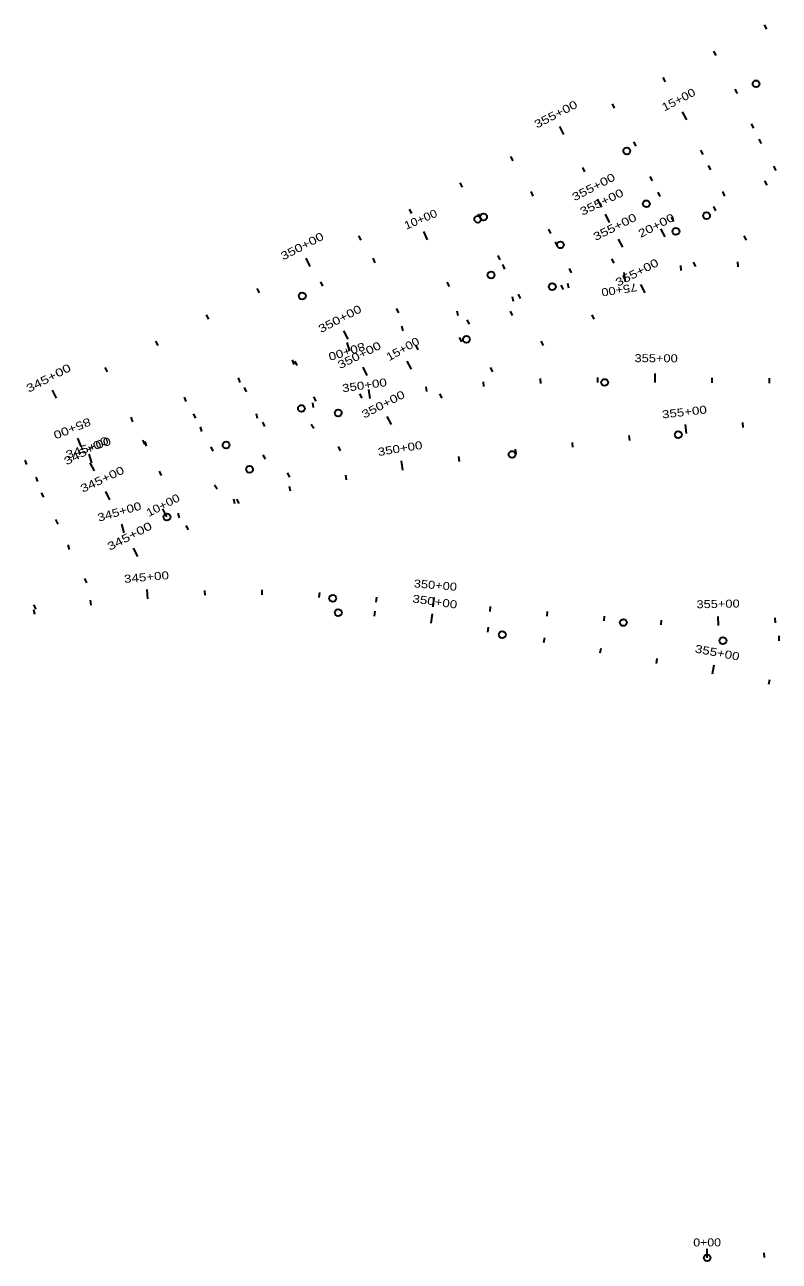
# Model space of a CAD drawing. Extents: x 2357892 to 2370172, y 6966790 to 6985499.
# Drawn here: x 2361944 to 2363264, y 6976486 to 6978648 of the extents above; entities that cross this region are included whole.
import ezdxf
from ezdxf.enums import TextEntityAlignment as Align

# ---------------------------------------------------------------- set-up
doc = ezdxf.new("R2010")
doc.units = 0
doc.header["$LTSCALE"] = 5.6
doc.layers.add('28', color=7, linetype='Continuous', lineweight=35)

msp = doc.modelspace()

# ---------------------------------------------------------------- linework, layer by layer
at = {"layer": '28'}
for p, q in [((2363242.374, 6978640.511), (2363238.454, 6978648.053)), ((2363153.644, 6978594.392), (2363149.724, 6978601.934)), ((2363064.914, 6978548.274), (2363060.994, 6978555.816)), ((2363190.97, 6978527.822), (2363187.05, 6978535.364)), ((2362976.183, 6978502.155), (2362972.263, 6978509.697)), ((2363102.237, 6978481.707), (2363094.859, 6978495.905)), ((2362887.453, 6978456.036), (2362880.074, 6978470.233)), ((2363219.718, 6978467.255), (2363215.798, 6978474.797)), ((2363233.133, 6978440.469), (2363229.189, 6978447.998)), ((2363013.505, 6978435.593), (2363009.585, 6978443.135)), ((2363130.985, 6978421.141), (2363127.065, 6978428.683)), ((2362798.723, 6978409.918), (2362794.803, 6978417.46)), ((2362924.238, 6978390.521), (2362920.535, 6978398.172)), ((2363042.252, 6978375.026), (2363038.333, 6978382.569)), ((2363144.553, 6978394.063), (2363140.608, 6978401.592)), ((2363258.451, 6978393.371), (2363254.64, 6978400.969)), ((2362709.992, 6978363.799), (2362706.072, 6978371.341)), ((2363242.718, 6978367.239), (2363238.902, 6978374.834)), ((2362833.477, 6978348.54), (2362830.043, 6978356.316)), ((2362953.52, 6978328.912), (2362946.142, 6978343.109)), ((2363055.972, 6978347.657), (2363052.028, 6978355.186)), ((2363169.063, 6978348.538), (2363165.253, 6978356.136)), ((2362621.262, 6978317.681), (2362617.342, 6978325.223)), ((2362741.308, 6978309.747), (2362738.132, 6978317.632)), ((2363153.362, 6978322.344), (2363149.546, 6978329.939)), ((2362966.869, 6978302.276), (2362959.897, 6978316.677)), ((2363079.676, 6978303.706), (2363075.865, 6978311.304)), ((2362532.532, 6978271.562), (2362528.611, 6978279.104)), ((2362648.849, 6978271.651), (2362642.625, 6978286.391)), ((2362864.787, 6978282.798), (2362860.868, 6978290.34)), ((2363064.251, 6978276.967), (2363056.918, 6978291.188)), ((2363206.786, 6978271.571), (2363202.867, 6978279.114)), ((2362875.943, 6978260.671), (2362872.556, 6978268.467)), ((2362990.289, 6978258.874), (2362983.116, 6978273.176)), ((2362443.801, 6978225.444), (2362436.422, 6978239.64)), ((2362557.068, 6978231.95), (2362553.625, 6978239.721)), ((2362776.055, 6978236.684), (2362772.135, 6978244.226)), ((2362975.372, 6978231.137), (2362971.476, 6978238.692)), ((2363118.045, 6978225.472), (2363114.127, 6978233.015)), ((2363191.153, 6978233.232), (2363191.43, 6978224.736)), ((2362784.224, 6978220.825), (2362780.838, 6978228.621)), ((2362900.902, 6978214.042), (2362897.091, 6978221.639)), ((2362992.154, 6978214.527), (2362994.621, 6978198.718)), ((2363091.368, 6978226.919), (2363092.163, 6978218.456)), ((2362465.994, 6978190.652), (2362462.416, 6978198.362)), ((2362687.322, 6978190.569), (2362683.402, 6978198.112)), ((2362886.492, 6978185.307), (2362882.596, 6978192.862)), ((2362893.883, 6978196.101), (2362895.703, 6978187.798)), ((2363029.305, 6978179.372), (2363021.929, 6978193.571)), ((2362355.071, 6978179.325), (2362351.151, 6978186.867)), ((2362796.633, 6978172.822), (2362798.697, 6978164.576)), ((2362811.515, 6978169.209), (2362807.704, 6978176.807)), ((2362598.589, 6978144.455), (2362594.67, 6978151.997)), ((2362699.844, 6978147.69), (2362702.052, 6978139.481)), ((2362797.612, 6978139.477), (2362793.717, 6978147.031)), ((2362266.34, 6978133.206), (2362262.42, 6978140.748)), ((2362722.128, 6978124.377), (2362718.317, 6978131.975)), ((2362940.565, 6978133.273), (2362936.646, 6978140.816)), ((2362509.857, 6978098.341), (2362502.479, 6978112.538)), ((2362603.508, 6978120.872), (2362605.859, 6978112.704)), ((2362708.739, 6978093.633), (2362704.82, 6978101.176)), ((2362177.61, 6978087.088), (2362173.69, 6978094.63)), ((2362507.655, 6978092.378), (2362512.348, 6978077.081)), ((2362632.74, 6978079.545), (2362628.93, 6978087.143)), ((2362851.825, 6978087.173), (2362847.906, 6978094.716)), ((2362412.314, 6978062.214), (2362414.948, 6978054.133)), ((2362421.124, 6978052.226), (2362417.205, 6978059.769)), ((2362620.83, 6978045.978), (2362612.961, 6978059.909)), ((2362088.88, 6978040.969), (2362084.96, 6978048.511)), ((2362543.353, 6978034.712), (2362536.18, 6978049.014)), ((2362763.084, 6978041.074), (2362759.166, 6978048.617)), ((2363046.916, 6978022.194), (2363046.969, 6978038.194)), ((2362317.514, 6978030.392), (2362320.289, 6978022.358)), ((2362647.475, 6978006.598), (2362646.581, 6978015.051)), ((2362747.084, 6978015.385), (2362746.484, 6978023.864)), ((2362846.938, 6978020.69), (2362846.635, 6978029.185)), ((2362946.916, 6978022.508), (2362946.91, 6978031.008)), ((2363146.915, 6978021.857), (2363146.944, 6978030.357)), ((2363246.914, 6978021.52), (2363246.943, 6978030.02)), ((2362000.149, 6977994.851), (2361992.77, 6978009.048)), ((2362223.283, 6977996.92), (2362226.198, 6977988.935)), ((2362332.392, 6978006.112), (2362328.472, 6978013.654)), ((2362453.966, 6977989.88), (2362450.155, 6977997.478)), ((2362534.638, 6977995.284), (2362530.202, 6978002.535)), ((2362548.235, 6977994.34), (2362545.996, 6978010.183)), ((2362674.344, 6977994.974), (2362670.426, 6978002.517)), ((2362449.482, 6977978.626), (2362448, 6977986.996)), ((2362129.651, 6977961.808), (2362132.705, 6977953.876)), ((2362243.659, 6977959.998), (2362239.739, 6977967.54)), ((2362351.338, 6977959.475), (2362349.565, 6977967.788)), ((2362364.382, 6977945.445), (2362360.666, 6977953.09)), ((2362585.604, 6977948.875), (2362578.228, 6977963.073)), ((2363201.172, 6977943.713), (2363200.333, 6977952.171)), ((2362253.922, 6977936.911), (2362251.86, 6977945.157)), ((2362450.027, 6977941.987), (2362445.465, 6977949.16)), ((2363002.456, 6977921.124), (2363001.448, 6977929.564)), ((2363101.753, 6977932.967), (2363099.895, 6977948.859)), ((2362036.647, 6977925.068), (2362042.655, 6977910.239)), ((2362154.926, 6977913.884), (2362151.007, 6977921.426)), ((2362157.353, 6977910.961), (2362155.005, 6977919.13)), ((2362274.089, 6977902.467), (2362270.474, 6977910.16)), ((2362496.864, 6977902.775), (2362492.945, 6977910.318)), ((2362903.162, 6977909.264), (2362902.154, 6977917.704)), ((2361944.297, 6977886.71), (2361947.626, 6977878.889)), ((2362061.749, 6977881.656), (2362056.794, 6977896.869)), ((2362365.642, 6977888.328), (2362361.081, 6977895.501)), ((2362605.857, 6977869.393), (2362603.249, 6977885.179)), ((2362704.7, 6977884.546), (2362703.51, 6977892.963)), ((2362803.868, 6977897.403), (2362802.86, 6977905.843)), ((2362066.194, 6977867.769), (2362058.816, 6977881.967)), ((2362183.585, 6977859.935), (2362179.97, 6977867.628)), ((2362408.123, 6977856.676), (2362404.205, 6977864.219)), ((2361967.225, 6977849.033), (2361964.313, 6977857.018)), ((2362280.645, 6977835.659), (2362276.337, 6977842.987)), ((2362507.394, 6977851.945), (2362505.813, 6977860.297)), ((2361977.461, 6977821.655), (2361973.542, 6977829.197)), ((2362093.081, 6977817.403), (2362086.276, 6977831.883)), ((2362409.362, 6977832.213), (2362407.588, 6977840.526)), ((2362193.151, 6977787.258), (2362185.776, 6977801.457)), ((2362311.816, 6977810.206), (2362309.849, 6977818.475)), ((2362319.383, 6977810.576), (2362315.465, 6977818.119)), ((2362002.577, 6977774.871), (2361998.961, 6977782.563)), ((2362214.808, 6977785.937), (2362212.649, 6977794.158)), ((2362118.391, 6977759.418), (2362113.968, 6977774.795)), ((2362230.643, 6977764.477), (2362226.724, 6977772.019)), ((2362022.616, 6977730.665), (2362020.077, 6977738.777)), ((2362141.903, 6977718.377), (2362134.527, 6977732.575)), ((2362053.162, 6977672.277), (2362049.244, 6977679.82)), ((2362159.914, 6977644.359), (2362158.534, 6977660.299)), ((2362259.722, 6977650.373), (2362259.433, 6977658.868)), ((2362359.707, 6977651.155), (2362359.863, 6977659.654)), ((2362459.597, 6977646.704), (2362460.197, 6977655.182)), ((2362559.264, 6977638.557), (2362559.969, 6977647.028)), ((2361964.422, 6977626.178), (2361960.504, 6977633.721)), ((2362060.558, 6977633.13), (2362059.383, 6977641.548)), ((2362658.92, 6977630.267), (2362660.246, 6977646.212)), ((2362758.576, 6977621.977), (2362759.28, 6977630.448)), ((2361961.926, 6977616.716), (2361960.312, 6977625.061)), ((2362556.211, 6977614.016), (2362557.104, 6977622.469)), ((2362655.454, 6977601.775), (2362657.69, 6977617.619)), ((2362858.231, 6977613.687), (2362858.936, 6977622.158)), ((2362957.887, 6977605.397), (2362958.592, 6977613.868)), ((2363057.636, 6977598.446), (2363057.997, 6977606.938)), ((2363157.613, 6977597.25), (2363157.316, 6977613.248)), ((2363257.477, 6977602.16), (2363256.801, 6977610.633)), ((2362754.21, 6977586.079), (2362755.69, 6977594.449)), ((2362852.541, 6977567.89), (2362854.097, 6977576.247)), ((2363264.113, 6977570.895), (2363263.877, 6977579.392)), ((2362950.852, 6977549.587), (2362952.408, 6977557.944)), ((2363049.163, 6977531.284), (2363050.718, 6977539.64)), ((2363147.473, 6977512.981), (2363150.402, 6977528.711)), ((2363245.784, 6977494.678), (2363247.34, 6977503.034)), ((2363137.992, 6976491.682), (2363137.939, 6976507.682)), ((2363237.991, 6976492.016), (2363237.963, 6976500.516))]:
    msp.add_line(p, q, dxfattribs=at)
for centre in [(2363223.591, 6978544.775), (2362997.458, 6978427.253), (2363031.737, 6978334.96), (2362746.814, 6978311.965), (2363136.926, 6978314.086), (2362736.748, 6978307.91), (2363083.321, 6978286.801), (2362881.381, 6978263.033), (2362759.919, 6978210.266), (2362867.127, 6978189.997), (2362429.768, 6978173.689), (2362716.922, 6978097.869), (2362958.646, 6978022.492), (2362428.312, 6977977.013), (2362492.639, 6977969.084), (2363087.548, 6977931.289), (2362296.528, 6977913.012), (2362796.833, 6977896.563), (2362337.537, 6977870.457), (2362193.151, 6977787.258), (2362482.978, 6977644.903), (2362492.705, 6977620.011), (2362991.483, 6977602.602), (2362779.558, 6977581.478), (2363165.667, 6977571.062), (2363137.992, 6976491.682)]:
    msp.add_circle(centre, 6, dxfattribs=at)

# ---------------------------------------------------------------- texts
for s, rotation, width, p in [('15+00', 27.461, 1.2, (2363091.17, 6978510.892)), ('355+00', 27.464, 1.3, (2362876.384, 6978485.221)), ('355+00', 27.461, 1.3, (2362942.452, 6978358.097)), ('355+00', 25.833, 1.3, (2362956.41, 6978331.655)), ('10+00', 22.892, 1.15, (2362639.514, 6978301.36)), ('355+00', 26.636, 1.3, (2362979.529, 6978288.157)), ('20+00', 27.278, 1.3, (2363052.188, 6978290.864)), ('350+00', 27.464, 1.3, (2362432.733, 6978254.628)), ('355+00', 27.451, 1.3, (2363018.241, 6978208.558)), ('75+00', 188.87, 1.2, (2362983.212, 6978191.365)), ('350+00', 27.461, 1.3, (2362498.79, 6978127.525)), ('15+00', 29.462, 1.2, (2362609.027, 6978074.914)), ('80+00', 197.056, 1.25, (2362505.587, 6978083.105)), ('350+00', 26.636, 1.3, (2362532.595, 6978063.997)), ('355+00', 359.807, 1.2, (2363048.704, 6978057.839)), ('345+00', 27.464, 1.35, (2361989.082, 6978024.036)), ('350+00', 8.041, 1.25, (2362539.439, 6978010.756)), ('350+00', 27.451, 1.3, (2362574.541, 6977978.061)), ('355+00', 6.669, 1.25, (2363098.966, 6977963.852)), ('85+00', 202.056, 1.3, (2362024.756, 6977948.478)), ('345+00', 27.461, 1.35, (2362055.128, 6977896.955)), ('345+00', 18.041, 1.3, (2362057.724, 6977901.379)), ('350+00', 9.382, 1.25, (2362601.945, 6977900.167)), ('345+00', 25.171, 1.3, (2362082.874, 6977846.858)), ('10+00', 27.451, 1.2, (2362189.283, 6977801.665)), ('345+00', 16.045, 1.25, (2362111.758, 6977789.767)), ('345+00', 27.451, 1.35, (2362130.839, 6977747.563)), ('345+00', 4.948, 1.25, (2362157.844, 6977675.296)), ('350+00', 355.245, 1.2, (2362662.07, 6977661.112)), ('350+00', 351.969, 1.25, (2362660.765, 6977632.333)), ('355+00', 1.065, 1.2, (2363157.167, 6977628.247)), ('355+00', 349.454, 1.25, (2363154.428, 6977543.219)), ('0+00', 0.191, 1.15, (2363137.949, 6976511.682))]:
    msp.add_text(s, height=14, rotation=rotation, dxfattribs=dict(at, width=width)).set_placement(p, align=Align.CENTER)

doc.saveas('drawing.dxf')
